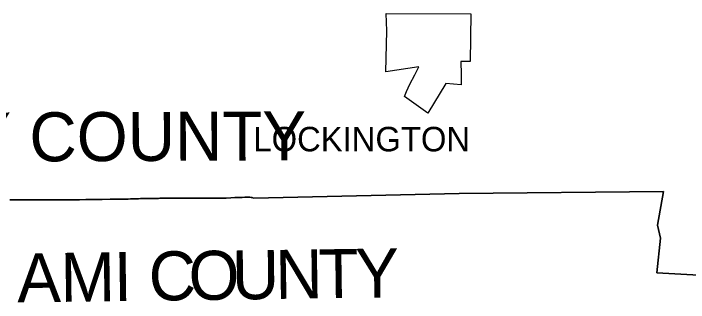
# Model space of a CAD drawing. Extents: x 0 to 34, y 0 to 22.
# Drawn here: x 5.0156 to 5.2369, y 17.7124 to 17.8072 of the extents above; entities that cross this region are included whole.
import ezdxf

# ---------------------------------------------------------------- set-up
doc = ezdxf.new("R2010")
doc.units = 0
for name, color, linetype in [('GM_X_Corporation', 7, 'Continuous'), ('GM_X_Corporation_Text', 7, 'Continuous'), ('GM_X_County', 7, 'Continuous'), ('GM_X_County_Text', 7, 'Continuous')]:
    doc.layers.add(name, color=color, linetype=linetype)

msp = doc.modelspace()

# ---------------------------------------------------------------- linework, layer by layer
at = {"layer": 'GM_X_Corporation'}
msp.add_lwpolyline([(5.16227, 17.79146), (5.16229, 17.79009), (5.16231, 17.78863), (5.16231, 17.78711), (5.16232, 17.78662), (5.16231, 17.78513), (5.1623, 17.78385), (5.15733, 17.78427), (5.15139, 17.77459), (5.14379, 17.78001), (5.14438, 17.78169), (5.14552, 17.78404), (5.14718, 17.78716), (5.14848, 17.7897), (5.13768, 17.78807), (5.13793, 17.8015), (5.13777, 17.80724), (5.16548, 17.80716), (5.16533, 17.79146), (5.16476, 17.79146), (5.16434, 17.79145), (5.16368, 17.79144), (5.16303, 17.79145)], close=True, dxfattribs=at)
at = {"layer": 'GM_X_County'}
for points in [[(5.25411, 17.72066), (5.22655, 17.72214), (5.22767, 17.7336), (5.22675, 17.73778), (5.22875, 17.7489), (5.16175, 17.74823), (5.09433, 17.74671), (5.09408, 17.74679), (5.0938, 17.74687), (5.09344, 17.74693), (5.09306, 17.74696), (5.0925, 17.74696), (5.09229, 17.74696), (5.09145, 17.74696), (5.09051, 17.74693), (5.08956, 17.7469), (5.08809, 17.74684), (5.08683, 17.74678), (5.08525, 17.74669), (5.08388, 17.74666), (5.08046, 17.74664), (5.07745, 17.74666), (5.07593, 17.74665), (5.07435, 17.74664), (5.07371, 17.74664), (5.07218, 17.74664), (5.06992, 17.74663), (5.0687, 17.74663), (5.06696, 17.74663), (5.06517, 17.74663), (5.06401, 17.74662), (5.06354, 17.74662), (5.06306, 17.74661), (5.06243, 17.74661), (5.06054, 17.74659), (5.05875, 17.74655), (5.05722, 17.74652), (5.05653, 17.7465), (5.05585, 17.74648), (5.05459, 17.74643), (5.05395, 17.74641), (5.05316, 17.74639), (5.05232, 17.74638), (5.0509, 17.74637), (5.04731, 17.74629), (5.04467, 17.74627), (5.04109, 17.74622), (5.0393, 17.7462), (5.03724, 17.74617), (5.03524, 17.74617), (5.03318, 17.74615), (5.03102, 17.74612), (5.02923, 17.7461), (5.02738, 17.7461), (5.02538, 17.7461), (5.02264, 17.74608), (5.01968, 17.74609), (5.01837, 17.74608), (5.01436, 17.74607)], [(5.01436, 17.74607), (5.01837, 17.74608), (5.01968, 17.74609), (5.02264, 17.74608), (5.02538, 17.7461), (5.02738, 17.7461), (5.02923, 17.7461), (5.03102, 17.74612), (5.03318, 17.74615), (5.03524, 17.74617), (5.03724, 17.74617), (5.0393, 17.7462), (5.04109, 17.74622), (5.04467, 17.74627), (5.04731, 17.74629), (5.0509, 17.74637), (5.05232, 17.74638), (5.05316, 17.74639), (5.05395, 17.74641), (5.05459, 17.74643), (5.05585, 17.74648), (5.05653, 17.7465), (5.05722, 17.74652), (5.05875, 17.74655), (5.06054, 17.74659), (5.06243, 17.74661), (5.06306, 17.74661), (5.06354, 17.74662), (5.06401, 17.74662), (5.06517, 17.74663), (5.06696, 17.74663), (5.0687, 17.74663), (5.06992, 17.74663), (5.07218, 17.74664), (5.07371, 17.74664), (5.07435, 17.74664), (5.07593, 17.74665), (5.07745, 17.74666), (5.08046, 17.74664), (5.08388, 17.74666), (5.08525, 17.74669), (5.08683, 17.74678), (5.08809, 17.74684), (5.08956, 17.7469), (5.09051, 17.74693), (5.09145, 17.74696), (5.09229, 17.74696), (5.0925, 17.74696), (5.09306, 17.74696), (5.09344, 17.74693), (5.0938, 17.74687), (5.09408, 17.74679), (5.09433, 17.74671), (5.16175, 17.74823), (5.22875, 17.7489), (5.22675, 17.73778), (5.22767, 17.7336), (5.22655, 17.72214), (5.25411, 17.72066)]]:
    msp.add_lwpolyline(points, dxfattribs=at)

# ---------------------------------------------------------------- texts
at = {"layer": 'GM_X_Corporation_Text'}
msp.add_text('LOCKINGTON', height=0.008037, rotation=0, dxfattribs=at).set_placement((5.09422, 17.76202))
at = {"layer": 'GM_X_County_Text'}
for s, height, rotation, p in [('SHELBY COUNTY', 0.016074, 0.2267, (4.93, 17.75836)), ('C', 0.01607, 0.7904, (5.05999, 17.71304)), ('O', 0.01607, 0.7906, (5.07307, 17.71322)), ('U', 0.01607, 0.7913, (5.08728, 17.71341)), ('N', 0.01607, 0.7906, (5.1015, 17.71361)), ('T', 0.01607, 0.7906, (5.11571, 17.7138)), ('Y', 0.01607, 0.7906, (5.12774, 17.71397)), ('A', 0.01607, 0.7624, (5.01684, 17.71245)), ('M', 0.01607, 0.7867, (5.03106, 17.71264)), ('I', 0.01607, 0.7941, (5.04853, 17.71288))]:
    msp.add_text(s, height=height, rotation=rotation, dxfattribs=at).set_placement(p)

doc.saveas('drawing.dxf')
